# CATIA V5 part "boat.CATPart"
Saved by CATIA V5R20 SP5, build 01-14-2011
Part number: Part1
Bounding box of the stored display mesh (mm): x -60 to 50, y -230 to 100, z 0 to 245.486
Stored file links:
  D:\3d零件\boat.CATPart
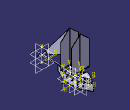
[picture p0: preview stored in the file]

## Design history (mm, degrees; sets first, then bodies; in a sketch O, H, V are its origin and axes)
Body1 (main body)
  Sketch1 on xy-plane, origin (0, 0, 0), H (1, 0, 0), V (0, 1, 0)
    point P1 (-30, 100)
    line L1 (30, 40) -> (30, -40)
    line L2 (-30, -40) -> (-30, 40)
    point P2 (30, -100)
    line L3 (-30, 40) -> (0, 100)
    line L4 (0, 100) -> (30, 40)
    line L5 (-30, -40) -> (0, -100)
    line L6 (30, -40) -> (0, -100)
    vertical: L1 V, L2 V
    parallelism: L5 L4, L6 L3
  Pad1: profile Sketch1, direction (0, 0, 1), length 40
  Sketch2 on end face of Pad1, origin (0, 0, 40), H (1, 0, 0), V (0, 1, 0)
    line L1 (0, 90) -> (-20, 50)
    line L2 (0, 90) -> (20, 50)
    line L3 (20, 50) -> (20, -50)
    line L4 (-20, 50) -> (-20, -50)
    line L5 (0, -90) -> (-20, -50)
    point P6 (0, -90)
    line L6 (20, -50) -> (0, -90)
    vertical: L3 V, L4 V
    coincidence: P6 V
    parallelism: L5 L2, L6 L1
  Pocket1: profile Sketch2, direction (0, 0, -1), length 35
  Sketch3 on face of Pocket1 from Sketch2.L4, origin (-20, 0, 0), H (0, 1, 0), V (0, 0, 1)
    line L1 (-50, 40) -> (50, 40)
    line L2 (50, 40) -> (50, 0)
    line L3 (50, 0) -> (-50, 0)
    line L4 (-50, 0) -> (-50, 40)
    point P3 (50, 0)
    horizontal: L1 H, L3 H
    vertical: L2 V, L4 V
    coincidence: P3 H
  Sketch4 on face of Pocket1 from Sketch2.L4, origin (-20, 0, 0), H (0, 1, 0), V (0, 0, 1)
  Sketch5 on end face of Pad1, origin (0, 0, 40), H (1, 0, 0), V (0, 1, 0)
    line L1 (-20, 50) -> (-25, 40)
    line L2 (-25, -40) -> (-25, 40)
    line L3 (-20, -50) -> (-25, -40)
    line L4 (20, 50) -> (25, 40)
    line L5 (20, -50) -> (25, -40)
    line L6 (25, -40) -> (25, 40)
    line L7 (-20, 50) -> (-20, -50)
    line L8 (20, 50) -> (20, -50)
    vertical: L2 V, L6 V, L7 V, L8 V
    parallelism: L5 L1
  Pocket2: profile Sketch5, direction (0, 0, -1), length 35
  Sketch6 on face of Pocket2, origin (0, 0, 5), H (1, 0, 0), V (0, 1, 0)
    point P1 (10, 50)
    point P2 (-10, 50)
    point P3 (25, 30)
    line L1 (-20, 40) -> (20, 40)
    line L2 (20, 40) -> (20, 50)
    line L3 (-20, 40) -> (-20, 50)
    line L4 (-20, 50) -> (0, 90)
    line L5 (20, 50) -> (0, 90)
    horizontal: L1 H
    vertical: L2 V, L3 V
  Pad2: profile Sketch6, direction (0, 0, 1), length 55
  Sketch7 on face of Pocket2, origin (0, 0, 5), H (1, 0, 0), V (0, 1, 0)
    line L1 (-20, 30) -> (20, 30)
    line L2 (20, 30) -> (20, -40)
    line L3 (20, -40) -> (-20, -40)
    line L4 (-20, -40) -> (-20, 30)
    horizontal: L1 H, L3 H
    vertical: L2 V, L4 V
  Pad3: profile Sketch7, direction (0, 0, 1), length 40
  Sketch8 on end face of Pad3, origin (0, 0, 45), H (1, 0, 0), V (0, 1, 0)
    line L1 (-10, 20) -> (10, 20)
    line L2 (10, 20) -> (10, -30)
    line L3 (10, -30) -> (-10, -30)
    line L4 (-10, -30) -> (-10, 20)
    horizontal: L1 H, L3 H
    vertical: L2 V, L4 V
  Pad4: profile Sketch8, direction (0, 0, 1), length 15
  Fillet1: radius 5, on edge [face of Pad1 from Sketch1.L5 | face of Pad1 from Sketch1.L2]; edge [face of Pad1 from Sketch1.L2 | face of Pad1 from Sketch1.L3]; edge [face of Pad1 from Sketch1.L4 | face of Pad1 from Sketch1.L1]; edge [face of Pad1 from Sketch1.L1 | face of Pad1 from Sketch1.L6]
  Fillet2: radius 5, on start face of Pad1
  Sketch9 on face of Pad3 from Sketch7.L3, origin (0, -40, 0), H (1, 0, 0), V (0, 0, 1)
    circle A1 centre (0, 40) radius 2.5
    radius A1 = 2.5
  Pad5: profile Sketch9, direction (0, -1, 0), length 150
  Plane1: type Offset, RefPlane zx-plane, Offset 190, reversed
  Sketch10 on Plane1, origin (0, -190, 0), H (-1, 0, 0), V (0, 0, 1)
    line L1 (-10, 0) -> (10, 0)
    point P1 (-10, 0)
    coincidence: P1 H
    horizontal: L1 H
  Plane2: type Angle, RefPlane Plane1, Direction Sketch10, Angle 90
  Plane3: type Offset, RefPlane Plane2, Offset 40, reversed
  Sketch11 on Plane3, origin (0, 0, 40), H (1, 0, 0), V (0, -1, 0)
    line L1 (-20, 190) -> (20, 190)
    horizontal: L1 H
  Plane4: type Angle, RefPlane Plane3, Direction Sketch11, Angle 90
  Sketch12 on Plane3, origin (0, 0, 40), H (1, 0, 0), V (0, -1, 0)
    line L1 (0, 190) -> (0, 210)
    point P1 (0, 190)
    line L2 (0, 210) -> (2.4041, 190)
    line L3 (2.4041, 190) -> (0, 190)
    coincidence: P1 V
    vertical: L1 V
    horizontal: L3 H
  Shaft1: profile Sketch12, axis Sketch12.L1, angle 360
  Sketch13 on end face of Pad3, origin (0, 0, 45), H (1, 0, 0), V (0, 1, 0)
    circle A1 centre (0, 25.0815) radius 2.5
    point P1 (0, 25.0815)
    circle A2 centre (0, -34.8576) radius 2.5
    point P2 (0, -34.8576)
    radius A1 = 2.5
    radius A2 = 2.5
    coincidence: P1 V, P2 V
  Pad6: profile Sketch13, direction (0, 0, 1), length 200
  Plane5: type Offset, RefPlane zx-plane, Offset 25
  Plane6: type Offset, RefPlane zx-plane, Offset 35, reversed
  Sketch14 on Plane5, origin (0, 25, 0), H (-1, 0, 0), V (0, 0, 1)
    line L1 (-30, 0) -> (20, 0)
    point P1 (-30, 0)
    coincidence: P1 H
    horizontal: L1 H
  Plane7: type Angle, RefPlane Plane5, Direction Sketch14, Angle 90
  Sketch15 on Plane6, origin (0, -35, 0), H (-1, 0, 0), V (0, 0, 1)
    line L1 (-40, 0) -> (60, 0)
    point P1 (-40, 0)
    coincidence: P1 H
    horizontal: L1 H
  Plane8: type Angle, RefPlane Plane6, Direction Sketch15, Angle 90
  Sketch16 on Plane7, origin (0, 0, 0), H (1, 0, 0), V (0, -1, 0)
    line L1 (0, -10) -> (0, -40)
    vertical: L1 V
  Plane9: type Angle, RefPlane Plane7, Direction Sketch16, Angle 90
  Sketch17 on Plane8, origin (0, 0, 0), H (1, 0, 0), V (0, -1, 0)
    line L1 (0, 50) -> (0, 20)
    point P1 (0, 50)
    coincidence: P1 V
    vertical: L1 V
  Plane10: type Angle, RefPlane Plane8, Direction Sketch17, Angle 90
  Sketch18 on Plane10, origin (0, 0, 0), H (0, -1, 0), V (0, 0, 1)
    circle A1 centre (34.8335, 65.3379) radius 2.5
    circle A2 centre (-25.1213, 65.3379) radius 2.5
    radius A1 = 2.5
    radius A2 = 2.5
  Pad7: profile Sketch18, direction (-1, 0, 0), length 50, mirrored extent
  Sketch19 on Plane6, origin (0, -35, 0), H (-1, 0, 0), V (0, 0, 1)
    line L1 (0, 245.4859) -> (50, 200)
    point P1 (0, 245.4859)
    line L2 (0, 245.4859) -> (-50, 200)
    point P3 (-50, 200)
    line L3 (50, 200) -> (50, 65.9211)
    line L4 (-50, 200) -> (-50, 65.9211)
    point P5 (-50, 200)
    line L5 (50, 65.9211) -> (-50, 65.9211)
    coincidence: P1 V, P5 L2, P3 P5
    vertical: L3 V, L4 V
    horizontal: L5 H
  Pad8: profile Sketch19, direction (0, 1, 0), length 0.5, mirrored extent
  Sketch20 on Plane5, origin (0, 25, 0), H (-1, 0, 0), V (0, 0, 1)
    line L1 (0, 244.6895) -> (40, 210)
    point P1 (0, 244.6895)
    line L2 (40, 210) -> (50, 201.3276)
    point P3 (50, 201.3276)
    line L3 (0, 244.6895) -> (-50, 201.3276)
    point P4 (-50, 201.3276)
    line L4 (50, 201.3276) -> (50, 66.208)
    point P5 (50, 66.208)
    line L5 (-50, 201.3276) -> (-50, 65.2198)
    point P6 (-50, 201.3276)
    line L6 (-50, 65.2198) -> (50, 66.208)
    point P8 (50, 66.208)
    coincidence: P1 V, P3 L1, P6 L3, L6 P5, P4 P6, P5 P8
    vertical: L4 V, L5 V
  Pad9: profile Sketch20, direction (0, 1, 0), length 0.5, mirrored extent
  Sketch21 on Plane3, origin (0, 0, 40), H (1, 0, 0), V (0, -1, 0)
    line L1 (0, 230) -> (0, 160)
    vertical: L1 V
  Plane11: type Angle, RefPlane Plane3, Direction Sketch21, Angle 90
  Sketch22 on Plane11, origin (0, 0, 0), H (0, -1, 0), V (0, 0, 1)
    line L1 (34.8242, 244.9346) -> (189.9532, 42.3403)
    point P1 (34.8242, 244.9346)
    line L2 (34.8242, 244.9346) -> (70.3067, 100.0865)
    point P3 (34.8242, 244.9346)
    line L3 (70.3067, 100.0865) -> (189.9532, 42.3403)
    coincidence: P3 L1, P1 P3
  Pad10: profile Sketch22, direction (-1, 0, 0), length 0.5, mirrored extent
  Sketch23 on face of Pad4 from Sketch8.L4, origin (-10, 0, 0), H (0, -1, 0), V (0, 0, 1)
    line L1 (-9.7401, 56.6405) -> (0, 56.6405)
    line L2 (0, 56.6405) -> (0, 50.2952)
    line L3 (0, 50.2952) -> (-9.7401, 50.2952)
    line L4 (-9.7401, 50.2952) -> (-9.7401, 56.6405)
    point P3 (0, 50.2952)
    point P5 (10.3183, 56.6405)
    line L5 (10.3183, 56.6405) -> (19.576, 56.6405)
    line L6 (19.576, 56.6405) -> (19.576, 50.2952)
    line L7 (19.576, 50.2952) -> (10.3183, 50.2952)
    line L8 (10.3183, 50.2952) -> (10.3183, 56.6405)
    point P7 (19.576, 50.2952)
    line L9 (-79.9445, 54.91) -> (-60.2718, 54.91)
    line L10 (-60.2718, 54.91) -> (-60.2718, 47.9878)
    line L11 (-60.2718, 47.9878) -> (-79.9445, 47.9878)
    line L12 (-79.9445, 47.9878) -> (-79.9445, 54.91)
    horizontal: L1 H, L3 H, L5 H, L7 H, L9 H, L11 H
    vertical: L2 V, L4 V, L6 V, L8 V, L10 V, L12 V
    coincidence: P3 V, P5 L1, P7 L3
  Pocket3: profile Sketch23, direction (1, 0, 0), length 100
